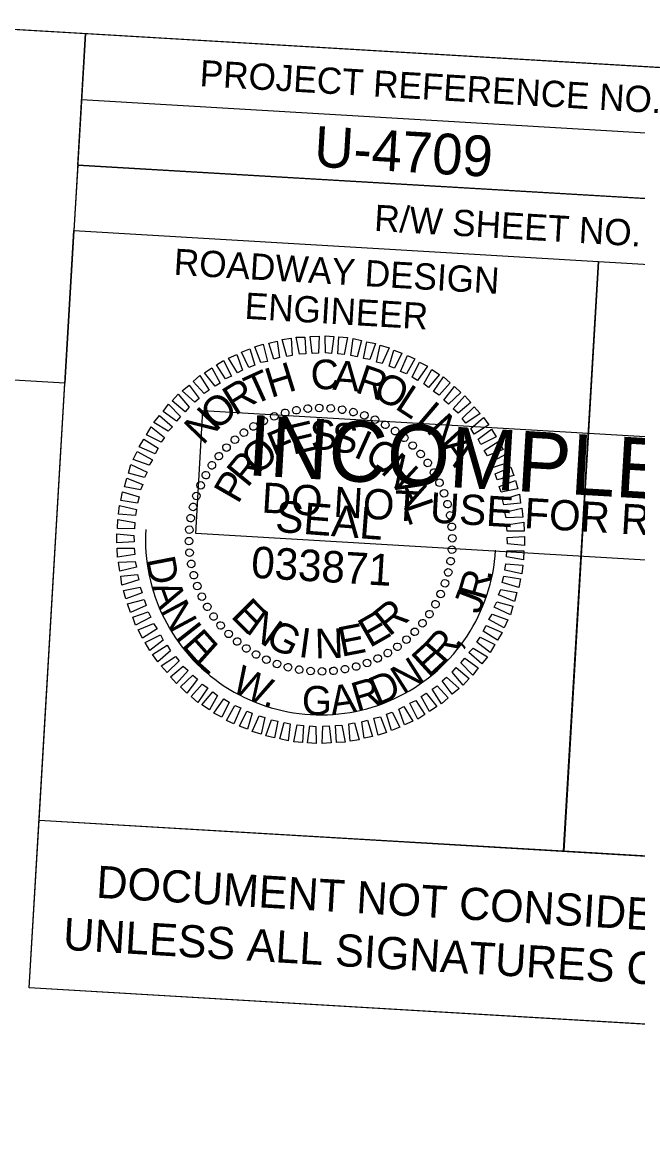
# Model space of a CAD drawing. Extents: x 2010737 to 2012732, y 444258 to 445456.
# Drawn here: x 2012494.2 to 2012611.3, y 445134 to 445346.8 of the extents above; entities that cross this region are included whole.
import ezdxf

# ---------------------------------------------------------------- set-up
doc = ezdxf.new("R2010")
doc.units = 0
for name, color, linetype in [('Old_Level_58', 7, 'Continuous'), ('Scratch_Level_0', 7, 'Continuous'), ('Sheet Clip Boundary CELL', 7, 'Continuous'), ('Sheet Data Field CELL', 7, 'Continuous'), ('Sheet Plan And Profile CELL', 7, 'Continuous'), ('Sheet Professional Seal CELL', 7, 'Continuous'), ('Sheet Profile Grid Minor CELL', 7, 'Continuous'), ('Sheet Sticker Exception Certification CELL', 7, 'Continuous'), ('Sheet Sticker Incomplete CELL', 7, 'Continuous')]:
    doc.layers.add(name, color=color, linetype=linetype)

msp = doc.modelspace()

# ---------------------------------------------------------------- linework, layer by layer
at = {"layer": 'Old_Level_58'}
msp.add_lwpolyline([(2012306.5, 445356.39), (2012506.21, 445344.62), (2012502.28, 445278.05), (2012302.58, 445289.82)], close=True, dxfattribs=at)
at = {"layer": 'Scratch_Level_0'}
msp.add_arc((2012550.99, 445248.27), 33.36, 176.6264, 356.6264, dxfattribs=at)
at = {"layer": 'Sheet Clip Boundary CELL'}
msp.add_lwpolyline([(2011147.85, 444375), (2012145.7, 444317.47), (2012151.4, 444414.1), (2011981.99, 444424.08), (2012065.05, 444531.98), (2012116.09, 444528.98), (2012447, 444433.71), (2012447.13, 444434.15), (2012512.37, 444430.3), (2012650.6, 444422.19), (2012665.49, 444675.78), (2012620.99, 444678.39), (2012629.52, 444823.68), (2012643.65, 445063.27), (2012648.58, 445153.9), (2012495.5, 445162.92), (2012502.28, 445278.05), (2012302.58, 445289.82), (2012278.52, 445262.33), (2012176.97, 445268.45), (2011765.99, 445293.2), (2011771.61, 445387.92), (2011477.93, 445405.24)], dxfattribs=at)
at = {"layer": 'Sheet Plan And Profile CELL'}
for p, q in [((2012505.47, 445332.09), (2012705.17, 445320.32)), ((2012504.73, 445319.61), (2012504, 445307.14)), ((2012504.73, 445319.61), (2012704.44, 445307.84)), ((2012603.87, 445301.25), (2012597.26, 445188.99))]:
    msp.add_line(p, q, dxfattribs=at)
for points in [[(2012705.91, 445332.85), (2011208.51, 445421.12), (2011146.72, 444372.94), (2012644.12, 444284.67)], [(2012506.21, 445344.62), (2012705.91, 445332.85), (2012704.44, 445307.84), (2012504.73, 445319.61)], [(2012504, 445307.14), (2012603.87, 445301.25), (2012597.25, 445188.94), (2012497.38, 445194.83)], [(2012603.87, 445301.25), (2012703.7, 445295.36), (2012697.08, 445183.06), (2012597.25, 445188.94)]]:
    msp.add_lwpolyline(points, close=True, dxfattribs=at)
at = {"layer": 'Sheet Professional Seal CELL'}
for p, q in [((2012550.71, 445273.38), (2012550.71, 445273.38)), ((2012542.15, 445271.78), (2012542.15, 445271.78)), ((2012544.2, 445272.46), (2012544.2, 445272.46)), ((2012546.33, 445272.94), (2012546.33, 445272.94)), ((2012548.55, 445273.21), (2012548.55, 445273.21)), ((2012552.91, 445273.3), (2012552.91, 445273.3)), ((2012555.1, 445273.02), (2012555.1, 445273.02)), ((2012557.22, 445272.55), (2012557.22, 445272.55)), ((2012559.29, 445271.97), (2012559.29, 445271.97)), ((2012538.18, 445269.86), (2012538.18, 445269.86)), ((2012540.15, 445270.9), (2012540.15, 445270.9)), ((2012561.35, 445271.15), (2012561.35, 445271.15)), ((2012563.29, 445270.14), (2012563.29, 445270.14)), ((2012534.63, 445267.32), (2012534.63, 445267.32)), ((2012536.36, 445268.72), (2012536.36, 445268.72)), ((2012565.18, 445269.02), (2012565.18, 445269.02)), ((2012566.9, 445267.67), (2012566.9, 445267.67)), ((2012533.04, 445265.86), (2012533.04, 445265.86)), ((2012568.57, 445266.22), (2012568.57, 445266.22)), ((2012531.59, 445264.19), (2012531.59, 445264.19)), ((2012570.03, 445264.63), (2012570.03, 445264.63)), ((2012571.43, 445262.89), (2012571.43, 445262.89)), ((2012530.23, 445262.47), (2012530.23, 445262.47)), ((2012572.58, 445261.07), (2012572.58, 445261.07)), ((2012528.11, 445258.64), (2012528.11, 445258.64)), ((2012529.12, 445260.58), (2012529.12, 445260.58)), ((2012573.61, 445259.11), (2012573.61, 445259.11)), ((2012527.28, 445256.58), (2012527.28, 445256.58)), ((2012574.5, 445257.1), (2012574.5, 445257.1)), ((2012526.71, 445254.51), (2012526.71, 445254.51)), ((2012575.18, 445255.06), (2012575.18, 445255.06)), ((2012526.23, 445252.39), (2012526.23, 445252.39)), ((2012575.65, 445252.93), (2012575.65, 445252.93)), ((2012525.96, 445250.2), (2012525.96, 445250.2)), ((2012575.92, 445250.71), (2012575.92, 445250.71)), ((2012525.88, 445248), (2012525.88, 445248)), ((2012550.99, 445248.27), (2012550.99, 445248.27)), ((2012576.09, 445248.54), (2012576.09, 445248.54)), ((2012526.05, 445245.84), (2012526.05, 445245.84)), ((2012576.02, 445246.35), (2012576.02, 445246.35)), ((2012526.32, 445243.62), (2012526.32, 445243.62)), ((2012575.74, 445244.16), (2012575.74, 445244.16)), ((2012526.79, 445241.48), (2012526.79, 445241.48)), ((2012575.26, 445242.03), (2012575.26, 445242.03)), ((2012527.47, 445239.44), (2012527.47, 445239.44)), ((2012574.69, 445239.96), (2012574.69, 445239.96)), ((2012528.36, 445237.43), (2012528.36, 445237.43)), ((2012573.87, 445237.91), (2012573.87, 445237.91)), ((2012529.39, 445235.47), (2012529.39, 445235.47)), ((2012572.85, 445235.96), (2012572.85, 445235.96)), ((2012530.54, 445233.65), (2012530.54, 445233.65)), ((2012571.74, 445234.08), (2012571.74, 445234.08)), ((2012531.94, 445231.91), (2012531.94, 445231.91)), ((2012570.38, 445232.35), (2012570.38, 445232.35)), ((2012533.4, 445230.33), (2012533.4, 445230.33)), ((2012535.07, 445228.88), (2012535.07, 445228.88)), ((2012567.34, 445229.23), (2012567.34, 445229.23)), ((2012568.93, 445230.69), (2012568.93, 445230.69)), ((2012536.79, 445227.52), (2012536.79, 445227.52)), ((2012563.79, 445226.68), (2012563.79, 445226.68)), ((2012565.61, 445227.83), (2012565.61, 445227.83)), ((2012538.68, 445226.41), (2012538.68, 445226.41)), ((2012540.62, 445225.39), (2012540.62, 445225.39)), ((2012542.68, 445224.57), (2012542.68, 445224.57)), ((2012559.82, 445224.76), (2012559.82, 445224.76)), ((2012561.82, 445225.64), (2012561.82, 445225.64)), ((2012544.75, 445224), (2012544.75, 445224)), ((2012546.87, 445223.52), (2012546.87, 445223.52)), ((2012549.06, 445223.24), (2012549.06, 445223.24)), ((2012551.26, 445223.16), (2012551.26, 445223.16)), ((2012553.42, 445223.34), (2012553.42, 445223.34)), ((2012555.64, 445223.61), (2012555.64, 445223.61)), ((2012557.77, 445224.08), (2012557.77, 445224.08))]:
    msp.add_line(p, q, dxfattribs=at)
for points in [[(2012544.53, 445283.16), (2012543.66, 445286.37), (2012545.38, 445286.62), (2012545.59, 445283.35)], [(2012546.96, 445283.57), (2012546.35, 445286.81), (2012548, 445286.86), (2012548.16, 445283.65)], [(2012549.37, 445283.73), (2012549.01, 445286.96), (2012550.72, 445287.05), (2012550.58, 445283.81)], [(2012551.88, 445283.83), (2012551.82, 445287.09), (2012553.47, 445286.94), (2012553.07, 445283.71)], [(2012554.27, 445283.64), (2012554.46, 445286.88), (2012556.11, 445286.74), (2012555.47, 445283.52)], [(2012556.76, 445283.34), (2012557.15, 445286.58), (2012558.78, 445286.18), (2012557.95, 445283.07)], [(2012537.34, 445281.08), (2012535.91, 445283.97), (2012537.5, 445284.58), (2012538.47, 445281.47)], [(2012539.6, 445282), (2012538.47, 445284.97), (2012540.01, 445285.48), (2012540.87, 445282.23)], [(2012542.09, 445282.65), (2012541.12, 445285.72), (2012542.7, 445286.08), (2012543.16, 445282.94)], [(2012559.13, 445282.8), (2012559.77, 445285.97), (2012561.4, 445285.62), (2012560.32, 445282.58)], [(2012561.64, 445282.1), (2012562.33, 445285.32), (2012564.01, 445284.82), (2012562.68, 445281.79)], [(2012564, 445281.31), (2012564.93, 445284.36), (2012566.45, 445283.77), (2012565.03, 445280.9)], [(2012532.86, 445278.89), (2012531.16, 445281.55), (2012532.51, 445282.42), (2012533.99, 445279.43)], [(2012535.13, 445280.01), (2012533.44, 445282.81), (2012535.03, 445283.52), (2012536.11, 445280.55)], [(2012566.2, 445280.28), (2012567.53, 445283.36), (2012568.89, 445282.68), (2012567.32, 445279.87)], [(2012568.39, 445279.2), (2012569.81, 445282.07), (2012571.31, 445281.28), (2012569.45, 445278.59)], [(2012530.87, 445277.51), (2012528.87, 445280.03), (2012530.28, 445281), (2012531.86, 445278.1)], [(2012570.61, 445277.92), (2012572.13, 445280.68), (2012573.58, 445279.75), (2012571.53, 445277.26)], [(2012527.03, 445274.43), (2012524.61, 445276.62), (2012525.92, 445277.7), (2012527.88, 445275.18)], [(2012528.78, 445276.08), (2012526.72, 445278.4), (2012527.98, 445279.53), (2012529.77, 445276.72)], [(2012572.48, 445276.46), (2012574.4, 445279.25), (2012575.63, 445278.12), (2012573.54, 445275.79)], [(2012525.17, 445272.63), (2012522.69, 445274.73), (2012523.87, 445275.97), (2012525.93, 445273.49)], [(2012574.44, 445274.84), (2012576.45, 445277.47), (2012577.68, 445276.3), (2012575.35, 445274.08)], [(2012576.24, 445273.18), (2012578.44, 445275.65), (2012579.57, 445274.38), (2012577.15, 445272.37)], [(2012523.56, 445270.82), (2012520.97, 445272.68), (2012522, 445274.07), (2012524.27, 445271.73)], [(2012577.94, 445271.33), (2012580.22, 445273.55), (2012581.35, 445272.28), (2012578.64, 445270.48)], [(2012521.95, 445268.92), (2012519.24, 445270.58), (2012520.32, 445271.92), (2012522.8, 445269.77)], [(2012579.58, 445269.43), (2012582.01, 445271.54), (2012582.98, 445270.13), (2012580.22, 445268.39)], [(2012520.63, 445266.84), (2012517.85, 445268.26), (2012518.69, 445269.76), (2012521.28, 445267.75)], [(2012580.96, 445267.39), (2012583.53, 445269.34), (2012584.39, 445267.84), (2012581.51, 445266.41)], [(2012519.49, 445264.6), (2012516.46, 445265.93), (2012517.3, 445267.44), (2012520.06, 445265.67)], [(2012582.14, 445265.27), (2012584.9, 445267.01), (2012585.76, 445265.46), (2012582.78, 445264.23)], [(2012518.36, 445262.47), (2012515.32, 445263.55), (2012516.06, 445265.06), (2012518.97, 445263.48)], [(2012583.31, 445263), (2012586.21, 445264.58), (2012586.76, 445262.99), (2012583.85, 445262.01)], [(2012517.47, 445260.11), (2012514.42, 445260.95), (2012514.86, 445262.57), (2012517.94, 445261.14)], [(2012584.18, 445260.79), (2012587.21, 445262.11), (2012587.77, 445260.48), (2012584.61, 445259.66)], [(2012516.68, 445257.76), (2012513.61, 445258.34), (2012514.06, 445260.01), (2012517.15, 445258.78)], [(2012584.94, 445258.39), (2012588.06, 445259.51), (2012588.52, 445257.93), (2012585.38, 445257.31)], [(2012516.13, 445255.23), (2012512.96, 445255.72), (2012513.26, 445257.41), (2012516.45, 445256.42)], [(2012585.6, 445255.95), (2012588.86, 445256.91), (2012589.06, 445255.24), (2012585.88, 445254.88)], [(2012515.74, 445252.85), (2012512.51, 445253.14), (2012512.7, 445254.79), (2012515.91, 445254.05)], [(2012586.05, 445253.52), (2012589.26, 445254.28), (2012589.45, 445252.57), (2012586.29, 445252.45)], [(2012515.55, 445250.36), (2012512.29, 445250.4), (2012512.39, 445252.1), (2012515.62, 445251.56)], [(2012586.36, 445251.09), (2012589.65, 445251.6), (2012589.7, 445249.9), (2012586.49, 445249.89)], [(2012515.45, 445247.86), (2012512.18, 445247.65), (2012512.18, 445249.36), (2012515.42, 445249.07)], [(2012586.52, 445248.68), (2012589.79, 445248.89), (2012589.79, 445247.19), (2012586.55, 445247.48)], [(2012515.61, 445245.45), (2012512.32, 445244.94), (2012512.27, 445246.65), (2012515.48, 445246.66)], [(2012586.42, 445246.18), (2012589.68, 445246.14), (2012589.58, 445244.44), (2012586.35, 445244.98)], [(2012515.92, 445243.03), (2012512.72, 445242.26), (2012512.52, 445243.98), (2012515.68, 445244.09)], [(2012586.23, 445243.69), (2012589.47, 445243.4), (2012589.27, 445241.76), (2012586.06, 445242.5)], [(2012516.37, 445240.6), (2012513.11, 445239.64), (2012512.91, 445241.3), (2012516.09, 445241.66)], [(2012585.84, 445241.31), (2012589.01, 445240.82), (2012588.71, 445239.14), (2012585.52, 445240.13)], [(2012517.03, 445238.15), (2012513.91, 445237.03), (2012513.45, 445238.61), (2012516.59, 445239.23)], [(2012585.29, 445238.79), (2012588.36, 445238.21), (2012587.91, 445236.53), (2012584.83, 445237.76)], [(2012517.79, 445235.75), (2012514.76, 445234.43), (2012514.2, 445236.07), (2012517.36, 445236.88)], [(2012584.5, 445236.43), (2012587.55, 445235.6), (2012587.11, 445233.97), (2012584.04, 445235.4)], [(2012518.66, 445233.55), (2012515.76, 445231.97), (2012515.21, 445233.55), (2012518.12, 445234.53)], [(2012583.61, 445234.08), (2012586.65, 445233), (2012585.91, 445231.49), (2012583, 445233.06)], [(2012519.83, 445231.28), (2012517.07, 445229.53), (2012516.21, 445231.09), (2012519.19, 445232.32)], [(2012582.48, 445231.94), (2012585.51, 445230.61), (2012584.67, 445229.11), (2012581.91, 445230.87)], [(2012521.01, 445229.15), (2012518.44, 445227.2), (2012517.58, 445228.7), (2012520.47, 445230.14)], [(2012581.35, 445229.7), (2012584.12, 445228.29), (2012583.28, 445226.78), (2012580.69, 445228.79)], [(2012522.39, 445227.12), (2012519.96, 445225.01), (2012518.99, 445226.42), (2012521.75, 445228.16)], [(2012580.02, 445227.63), (2012582.73, 445225.97), (2012581.65, 445224.63), (2012579.17, 445226.78)], [(2012524.03, 445225.22), (2012521.75, 445223), (2012520.62, 445224.27), (2012523.33, 445226.06)], [(2012578.41, 445225.72), (2012581, 445223.86), (2012579.97, 445222.47), (2012577.7, 445224.81)], [(2012525.73, 445223.37), (2012523.53, 445220.89), (2012522.4, 445222.16), (2012524.82, 445224.17)], [(2012527.53, 445221.71), (2012525.52, 445219.07), (2012524.29, 445220.24), (2012526.62, 445222.46)], [(2012576.8, 445223.91), (2012579.28, 445221.81), (2012578.1, 445220.58), (2012576.04, 445223.05)], [(2012529.49, 445220.09), (2012527.57, 445217.3), (2012526.34, 445218.42), (2012528.43, 445220.75)], [(2012573.19, 445220.47), (2012575.25, 445218.14), (2012573.99, 445217.01), (2012572.2, 445219.82)], [(2012574.94, 445222.12), (2012577.36, 445219.92), (2012576.05, 445218.85), (2012574.09, 445221.37)], [(2012531.36, 445218.63), (2012529.84, 445215.86), (2012528.39, 445216.8), (2012530.44, 445219.28)], [(2012571.1, 445219.04), (2012573.1, 445216.52), (2012571.7, 445215.55), (2012570.11, 445218.44)], [(2012533.59, 445217.34), (2012532.16, 445214.47), (2012530.66, 445215.26), (2012532.52, 445217.96)], [(2012535.78, 445216.26), (2012534.44, 445213.18), (2012533.08, 445213.87), (2012534.65, 445216.68)], [(2012566.85, 445216.53), (2012568.53, 445213.73), (2012566.94, 445213.02), (2012565.86, 445215.99)], [(2012569.11, 445217.65), (2012570.81, 445215), (2012569.46, 445214.13), (2012567.98, 445217.12)], [(2012537.97, 445215.23), (2012537.04, 445212.18), (2012535.52, 445212.77), (2012536.94, 445215.64)], [(2012540.33, 445214.44), (2012539.64, 445211.23), (2012537.96, 445211.72), (2012539.29, 445214.75)], [(2012542.84, 445213.74), (2012542.2, 445210.57), (2012540.57, 445210.92), (2012541.65, 445213.96)], [(2012559.88, 445213.89), (2012560.85, 445210.83), (2012559.28, 445210.47), (2012558.81, 445213.6)], [(2012562.37, 445214.54), (2012563.5, 445211.57), (2012561.96, 445211.06), (2012561.1, 445214.32)], [(2012564.63, 445215.46), (2012566.06, 445212.57), (2012564.47, 445211.97), (2012563.5, 445215.08)], [(2012545.21, 445213.2), (2012544.82, 445209.97), (2012543.19, 445210.36), (2012544.03, 445213.47)], [(2012547.7, 445212.9), (2012547.51, 445209.66), (2012545.86, 445209.81), (2012546.5, 445213.02)], [(2012550.09, 445212.71), (2012550.15, 445209.45), (2012548.51, 445209.6), (2012548.9, 445212.83)], [(2012552.6, 445212.82), (2012552.96, 445209.59), (2012551.25, 445209.49), (2012551.39, 445212.74)], [(2012555.02, 445212.97), (2012555.63, 445209.73), (2012553.97, 445209.68), (2012553.81, 445212.89)], [(2012557.44, 445213.38), (2012558.31, 445210.18), (2012556.59, 445209.93), (2012556.38, 445213.19)]]:
    msp.add_lwpolyline(points, close=True, dxfattribs=at)
for centre, major_axis in [((2012546.36, 445272.92), (-0.133, 0.708)), ((2012548.53, 445273.23), (-0.071, 0.717)), ((2012550.71, 445273.35), (-0.008, 0.72)), ((2012552.9, 445273.28), (0.055, 0.718)), ((2012555.07, 445273.02), (0.117, 0.71)), ((2012557.21, 445272.57), (0.179, 0.697)), ((2012540.14, 445270.88), (-0.311, 0.649)), ((2012542.15, 445271.74), (-0.254, 0.674)), ((2012544.23, 445272.42), (-0.194, 0.693)), ((2012559.3, 445271.93), (0.239, 0.679)), ((2012561.34, 445271.12), (0.297, 0.656)), ((2012536.38, 445268.66), (-0.419, 0.585)), ((2012538.21, 445269.85), (-0.367, 0.62)), ((2012563.29, 445270.13), (0.353, 0.627)), ((2012565.15, 445268.97), (0.407, 0.594)), ((2012534.66, 445267.31), (-0.469, 0.546)), ((2012566.9, 445267.66), (0.457, 0.557)), ((2012568.52, 445266.2), (0.504, 0.515)), ((2012531.6, 445264.18), (-0.557, 0.457)), ((2012533.06, 445265.81), (-0.515, 0.504)), ((2012570.02, 445264.6), (0.546, 0.469)), ((2012530.28, 445262.43), (-0.594, 0.407)), ((2012571.37, 445262.88), (0.585, 0.419)), ((2012529.13, 445260.57), (-0.627, 0.353)), ((2012572.57, 445261.05), (0.62, 0.367)), ((2012528.14, 445258.62), (-0.656, 0.297)), ((2012573.6, 445259.12), (0.649, 0.311)), ((2012527.33, 445256.59), (-0.679, 0.239)), ((2012574.46, 445257.11), (0.674, 0.254)), ((2012526.69, 445254.5), (-0.697, 0.179)), ((2012575.14, 445255.03), (0.693, 0.194)), ((2012526.24, 445252.36), (-0.71, 0.117)), ((2012575.64, 445252.9), (0.708, 0.133)), ((2012525.98, 445250.18), (-0.718, 0.055)), ((2012575.94, 445250.73), (0.717, 0.071)), ((2012525.91, 445248), (-0.72, -0.008)), ((2012576.06, 445248.55), (0.72, 0.008)), ((2012526.03, 445245.81), (-0.717, -0.071)), ((2012575.99, 445246.36), (0.718, -0.055)), ((2012526.34, 445243.65), (-0.708, -0.133)), ((2012575.73, 445244.19), (0.71, -0.117)), ((2012526.83, 445241.52), (-0.693, -0.194)), ((2012575.28, 445242.05), (0.697, -0.179)), ((2012527.51, 445239.44), (-0.674, -0.254)), ((2012574.65, 445239.95), (0.679, -0.239)), ((2012528.37, 445237.42), (-0.649, -0.311)), ((2012573.83, 445237.92), (0.656, -0.297)), ((2012529.4, 445235.5), (-0.62, -0.367)), ((2012572.84, 445235.97), (0.627, -0.353)), ((2012530.6, 445233.66), (-0.585, -0.419)), ((2012570.37, 445232.36), (0.557, -0.457)), ((2012571.69, 445234.11), (0.594, -0.407)), ((2012531.95, 445231.94), (-0.546, -0.469)), ((2012533.45, 445230.34), (-0.504, -0.515)), ((2012568.91, 445230.73), (0.515, -0.504)), ((2012535.08, 445228.88), (-0.457, -0.557)), ((2012565.59, 445227.89), (0.419, -0.585)), ((2012567.32, 445229.24), (0.469, -0.546)), ((2012536.83, 445227.57), (-0.407, -0.594)), ((2012538.68, 445226.42), (-0.353, -0.627)), ((2012563.76, 445226.69), (0.367, -0.62)), ((2012540.64, 445225.43), (-0.297, -0.656)), ((2012542.67, 445224.61), (-0.239, -0.679)), ((2012544.76, 445223.98), (-0.179, -0.697)), ((2012557.74, 445224.12), (0.194, -0.693)), ((2012559.82, 445224.8), (0.254, -0.674)), ((2012561.83, 445225.66), (0.311, -0.649)), ((2012546.9, 445223.53), (-0.117, -0.71)), ((2012549.07, 445223.26), (-0.055, -0.718)), ((2012551.26, 445223.19), (0.008, -0.72)), ((2012553.44, 445223.31), (0.071, -0.717)), ((2012555.61, 445223.62), (0.133, -0.708))]:
    msp.add_ellipse(centre, major_axis=major_axis, ratio=0.999708, dxfattribs=at)
at = {"layer": 'Sheet Sticker Exception Certification CELL'}
for p, q in [((2012495.5, 445162.92), (2012497.38, 445194.85)), ((2012497.38, 445194.85), (2012697.08, 445183.08)), ((2012695.2, 445151.15), (2012495.5, 445162.92))]:
    msp.add_line(p, q, dxfattribs=at)
at = {"layer": 'Sheet Sticker Incomplete CELL'}
msp.add_lwpolyline([(2012527.19, 445249.42), (2012528.57, 445272.88), (2012675.32, 445264.23), (2012673.94, 445240.77)], close=True, dxfattribs=at)

# ---------------------------------------------------------------- texts
at = {"layer": 'Sheet Data Field CELL'}
msp.add_text('U-4709', height=7.75, rotation=356.6264, dxfattribs=at).set_placement((2012549.59, 445319.32))
at = {"layer": 'Sheet Plan And Profile CELL'}
for s, height, p in [('PROJECT REFERENCE NO.', 5.0001, (2012527.86, 445334.63)), ('R/W SHEET NO.', 5.0001, (2012561.09, 445307.08)), ('ROADWAY DESIGN', 5.0001, (2012522.93, 445298.71)), ('ENGINEER', 5, (2012536.42, 445290.35))]:
    msp.add_text(s, height=height, rotation=356.6264, dxfattribs=at).set_placement(p)
at = {"layer": 'Sheet Professional Seal CELL'}
for s, height, rotation, p in [('H', 5.64, 17.2459, (2012541.51, 445275.23)), ('C', 5.64, 2.8463, (2012549.21, 445276.78)), ('A', 5.64, 355.6467, (2012553.17, 445276.84)), ('T', 5.64, 24.4462, (2012538.16, 445273.77)), ('R', 5.64, 341.2475, (2012557.35, 445276.4)), ('O', 5.64, 334.0476, (2012560.65, 445275.45)), ('R', 5.64, 31.6469, (2012534.64, 445271.77)), ('L', 5.64, 326.8473, (2012564.93, 445273.34)), ('O', 5.64, 38.8482, (2012531.01, 445268.88)), ('N', 5.64, 46.0499, (2012528.55, 445266.12)), ('I', 5.64, 319.6466, (2012568.84, 445270.71)), ('N', 5.64, 312.4453, (2012570.89, 445269.04)), ('F', 5.64, 22.5935, (2012542.39, 445263.1)), ('E', 5.64, 13.2375, (2012545.68, 445264.41)), ('S', 5.64, 3.882, (2012549.18, 445265.26)), ('S', 5.64, 354.5268, (2012552.78, 445265.1)), ('O', 5.64, 41.3077, (2012538.93, 445260.35)), ('I', 5.64, 335.816, (2012557.03, 445264.14)), ('O', 5.64, 326.4599, (2012558.99, 445263.33)), ('A', 5.64, 305.2436, (2012573.66, 445265.92)), ('N', 5.64, 317.103, (2012562.21, 445261.13)), ('R', 5.64, 50.6661, (2012537.03, 445258.01)), ('P', 5.64, 60.0253, (2012535.25, 445254.91)), ('A', 5.64, 298.3867, (2012564.9, 445258.37)), ('SEAL', 5.998, 355.6264, (2012542.21, 445249.79)), ('L', 5.64, 289.0273, (2012566.65, 445254.81)), ('E', 5.64, 314.9033, (2012533.69, 445233.61)), ('R', 5.64, 39.1078, (2012564.02, 445229.72)), ('N', 5.64, 324.2604, (2012536.53, 445230.74)), ('E', 5.64, 29.7505, (2012560.33, 445227.59)), ('G', 5.64, 333.6167, (2012540.19, 445228.27)), ('I', 5.64, 352.3276, (2012546.62, 445225.99)), ('N', 5.64, 1.6828, (2012549.95, 445225.64)), ('E', 5.64, 11.0382, (2012554.93, 445225.95))]:
    msp.add_text(s, height=height, rotation=rotation, dxfattribs=at).set_placement(p)
at = {"layer": 'Sheet Profile Grid Minor CELL'}
for s, height, rotation, p in [('033871', 5.998, 356.6264, (2012537.64, 445241.04)), ('D', 5.5, 280.8946, (2012517.72, 445244.58)), ('R', 5.5, 73.9805, (2012582.32, 445236.51)), ('.', 5.5, 80.9069, (2012583.51, 445240.37)), ('A', 5.5, 290.0393, (2012518.73, 445239.34)), ('J', 5.5, 69.1119, (2012581.21, 445233.89)), ('N', 5.5, 298.2251, (2012520.33, 445234.84)), ('I', 5.5, 308.1568, (2012523.11, 445229.75)), ('E', 5.5, 311.6772, (2012524.3, 445228.08)), ('R', 5.5, 49.0052, (2012574.42, 445224.38)), ('L', 5.5, 318.2602, (2012526.79, 445225.15)), ('E', 5.5, 42.4222, (2012571.53, 445221.85)), (',', 5.5, 55.9317, (2012577.13, 445227.38)), ('W', 5.5, 333.5156, (2012533.72, 445219.6)), ('N', 5.5, 32.4905, (2012566.66, 445218.7)), ('D', 5.5, 23.3459, (2012561.76, 445216.58)), ('G', 5.5, 358.3019, (2012547.34, 445215)), ('A', 5.5, 8.2337, (2012553.13, 445214.87)), ('R', 5.5, 16.4194, (2012557.86, 445215.52)), ('.', 5.5, 345.1217, (2012539.85, 445216.71))]:
    msp.add_text(s, height=height, rotation=rotation, dxfattribs=at).set_placement(p)
at = {"layer": 'Sheet Sticker Exception Certification CELL'}
for s, p in [('DOCUMENT NOT CONSIDERED FINAL', (2012508.16, 445180.11)), ('UNLESS ALL SIGNATURES COMPLETED', (2012501.83, 445170.2))]:
    msp.add_text(s, height=6.124, rotation=356.6264, dxfattribs=at).set_placement(p)
at = {"layer": 'Sheet Sticker Incomplete CELL'}
for s, height, p in [('INCOMPLETE PLANS', 11.52, (2012536.81, 445260.57)), ('DO NOT USE FOR R/W ACQUISITION', 5.76, (2012539.65, 445253.45))]:
    msp.add_text(s, height=height, rotation=356.6264, dxfattribs=at).set_placement(p)

doc.saveas('drawing.dxf')
